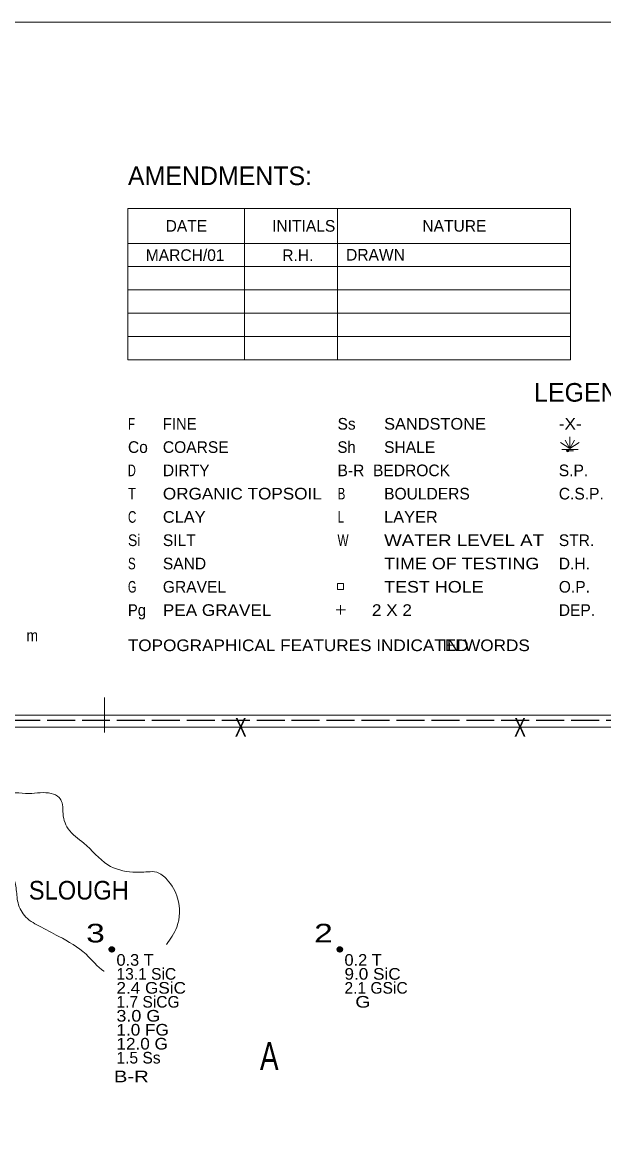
# Model space of a CAD drawing. Extents: x -577 to 499, y -450 to 700.
# Drawn here: x -35.4 to 214.3, y 225.1 to 700 of the extents above; entities that cross this region are included whole.
import ezdxf
from ezdxf.enums import TextEntityAlignment as Align

# ---------------------------------------------------------------- set-up
doc = ezdxf.new("R2010")
doc.units = 0
doc.header["$LTSCALE"] = 2
doc.header["$PDMODE"] = 32
doc.header["$PDSIZE"] = 1
doc.linetypes.add('LONG_DASHED', pattern=[7.5, 6, -1.5])
for name, color, linetype, lineweight in [('1', 7, 'Continuous', 13), ('2', 7, 'Continuous', 35), ('3', 7, 'Continuous', 13), ('4', 7, 'Continuous', 25)]:
    doc.layers.add(name, color=color, linetype=linetype, lineweight=lineweight)

msp = doc.modelspace()

# ---------------------------------------------------------------- linework, layer by layer
at = {"layer": '1'}
for p, q in [((199.983, 619.973), (9.983, 619.973)), ((9.983, 619.973), (9.983, 554.973)), ((59.983, 619.973), (59.983, 554.973)), ((99.983, 619.973), (99.983, 554.973)), ((199.983, 554.973), (199.983, 619.973)), ((9.983, 604.973), (199.983, 604.973)), ((9.983, 594.973), (199.983, 594.973)), ((9.983, 584.973), (199.983, 584.973)), ((9.983, 574.973), (199.983, 574.973)), ((9.983, 564.973), (199.983, 564.973)), ((199.76, 516.875), (195.76, 519.375)), ((199.76, 516.875), (197.76, 520.375)), ((199.76, 516.875), (199.76, 521.875)), ((199.76, 516.875), (201.76, 520.375)), ((199.76, 516.875), (203.76, 519.375)), ((196.26, 516.375), (203.26, 516.375)), ((198.26, 515.875), (201.26, 515.875)), ((103.353, 447.618), (99.353, 447.618)), ((101.291, 449.597), (101.291, 445.597)), ((-0.017, 394.973), (-0.017, 409.973))]:
    msp.add_line(p, q, dxfattribs=at)
for points in [[(449.983, -450.027), (449.983, 399.973), (449.983, 699.973), (-450.017, 699.973), (-450.017, 49.973), (-450.017, -450.027)], [(9.983, 554.973), (99.983, 554.973), (199.983, 554.973)], [(402.281, -402.333), (402.281, 402.339), (-402.391, 402.339)]]:
    msp.add_lwpolyline(points, dxfattribs=at)
msp.add_lwpolyline([(99.967, 456.301), (99.967, 458.832), (102.499, 458.832), (102.499, 456.301)], close=True, dxfattribs=at)
msp.add_point((198.76, 515.875), dxfattribs=at)
at = {"layer": '2', "linetype": 'LONG_DASHED', "lineweight": 25}
msp.add_lwpolyline([(302.281, 400), (-302.391, 400), (-302.391, 340.778)], dxfattribs=at)
at = {"layer": '2'}
for centre in [(3.055, 301.751), (100.962, 301.751)]:
    msp.add_circle(centre, 1, dxfattribs=at)
for points in [[(3.045, 302.638), (3.775, 302.234), (3.927, 301.386), (3.241, 300.858), (2.433, 301.088), (2.146, 301.846), (2.393, 302.408), (2.966, 302.576), (3.64, 302.082), (3.623, 301.341), (3.107, 301.082), (2.584, 301.251), (2.36, 301.897), (2.944, 302.363), (3.382, 301.829), (3.342, 301.346), (2.713, 301.481), (2.859, 302.116), (3.152, 301.565)], [(100.951, 302.638), (101.682, 302.234), (101.833, 301.386), (101.148, 300.858), (100.339, 301.088), (100.053, 301.846), (100.3, 302.408), (100.873, 302.576), (101.547, 302.082), (101.53, 301.341), (101.013, 301.082), (100.491, 301.251), (100.266, 301.897), (100.85, 302.363), (101.288, 301.829), (101.249, 301.346), (100.62, 301.481), (100.766, 302.116), (101.058, 301.565)]]:
    msp.add_spline(points, degree=3, dxfattribs=at)
at = {"layer": '2', "linetype": 'LONG_DASHED', "lineweight": 25}
msp.add_spline([(-281.328, 231.83), (-241.679, 217.766), (-223.152, 212.214), (-193.508, 201.481), (-159.789, 189.267), (-142.373, 182.975), (-121.622, 170.021), (-93.831, 153.735), (-76.045, 143.372), (-61.223, 137.08), (-27.503, 125.977), (-5.271, 120.055), (10.663, 117.094), (19.186, 115.613), (29.19, 118.204), (41.048, 124.496), (50.682, 128.937), (63.281, 140.411)], degree=3, dxfattribs=at)
at = {"layer": '3'}
msp.add_line((402.29, 397.182), (-112.541, 397.182), dxfattribs=at)
for points in [[(-45.877, 365.692), (-43.309, 367.937), (-32.557, 368.738), (-22.927, 368.738), (-19.557, 366.975), (-18.273, 364.731), (-17.952, 361.044), (-15.705, 353.51), (-8.965, 347.418), (1.306, 338.121), (12.059, 334.914), (18.479, 335.075), (22.33, 334.914), (26.824, 331.708), (31.318, 323.693), (30.997, 311.35), (26.537, 303.9)], [(-0.255, 292.406), (-0.299, 292.434), (-8.002, 299.648), (-19.718, 307.343), (-28.223, 311.831), (-34.483, 316.319), (-37.371, 322.571), (-38.174, 328.983), (-42.507, 339.724), (-46.519, 356.876), (-45.877, 365.212)]]:
    msp.add_spline(points, degree=3, dxfattribs=at)

# ---------------------------------------------------------------- texts
at = {"layer": '1'}
for s, height, p in [('AMENDMENTS:', 8, (9.983, 629.973)), ('Ss', 5, (99.983, 524.973)), ('Co', 5, (9.983, 514.973)), ('COARSE', 5, (24.983, 514.973)), ('SHALE', 5, (119.983, 514.973)), ('DIRTY', 5, (24.983, 504.973)), ('B-R  BEDROCK', 5, (99.983, 504.973)), ('S.P.', 5, (194.983, 504.973)), ('BOULDERS', 5, (119.983, 494.973)), ('C.S.P.', 5, (194.983, 494.973)), ('SILT', 5, (24.983, 474.973)), ('STR.', 5, (194.983, 474.973)), ('SAND', 5, (24.983, 464.973)), ('D.H.', 5, (194.983, 464.973)), ('GRAVEL', 5, (24.983, 454.973)), ('O.P.', 5, (194.983, 454.973)), ('DEP.', 5, (194.983, 444.973))]:
    msp.add_text(s, height=height, dxfattribs=at).set_placement(p)
for s, height, p in [('DATE', 5, (35.081, 609.973)), ('INITIALS', 5, (85.453, 609.973)), ('NATURE', 5, (150.16, 609.973)), ('MARCH/01', 5, (34.552, 597.405)), ('R.H.', 5, (82.941, 597.343)), ('DRAWN', 5, (116.266, 597.567)), ('LEGEND', 8, (206.378, 536.973))]:
    msp.add_text(s, height=height, dxfattribs=at).set_placement(p, align=Align.CENTER)
for s, width, p in [('F', 0.75, (9.983, 524.973)), ('FINE', 0.95, (24.983, 524.973)), ('SANDSTONE', 1.05, (119.983, 524.973)), ('-X-', 1.1, (194.983, 524.973)), ('Sh', 0.95, (99.983, 514.973)), ('D', 0.7, (9.983, 504.973)), ('T', 0.85, (9.983, 494.973)), ('ORGANIC TOPSOIL', 1.1, (24.983, 494.973)), ('B', 0.75, (99.983, 494.973)), ('C', 0.75, (9.983, 484.973)), ('CLAY', 1.05, (24.983, 484.973)), ('L', 0.75, (99.983, 484.973)), ('LAYER', 1.05, (119.983, 484.973)), ('Si', 0.9, (9.983, 474.973)), ('W', 0.75, (99.983, 474.973)), ('WATER LEVEL AT', 1.2, (119.983, 474.973)), ('S', 0.75, (9.983, 464.973)), ('TIME OF TESTING', 1.15, (119.983, 464.973)), ('G', 0.7, (9.983, 454.973)), ('TEST HOLE', 1.15, (119.983, 454.973)), ('Pg', 0.95, (9.983, 444.973)), ('PEA GRAVEL', 1.1, (24.983, 444.973)), ('   2 X 2', 1.1, (108.608, 444.973)), ('m', 0.9, (-33.607, 434.073)), ('TOPOGRAPHICAL FEATURES INDICATED', 1.1, (9.942, 429.855)), ('IN WORDS', 1.1, (144.942, 429.855))]:
    msp.add_text(s, height=5, dxfattribs=dict(at, width=width)).set_placement(p)
at = {"layer": '2', "width": 1.35}
for s, p in [('  3', (0.055, 304.751)), ('  2', (97.962, 304.751))]:
    msp.add_text(s, height=8, dxfattribs=at).set_placement(p, align=Align.RIGHT)
at = {"layer": '2'}
for s, width, p in [('0.3 T      ', 1.05, (5.055, 294.751)), ('0.2 T      ', 1.05, (102.962, 294.751)), ('9.0 SiC    ', 1.1, (102.962, 288.751)), ('2.4 GSiC   ', 1.1, (5.055, 282.751)), ('  G        ', 1.25, (102.962, 276.751)), ('3.0 G      ', 1.15, (5.055, 270.751)), ('1.0 FG     ', 1.1, (5.055, 264.751)), ('12.0 G     ', 1.1, (5.055, 258.751)), ('  B-R      ', 1.3, (-0.871, 244.712))]:
    msp.add_text(s, height=5, dxfattribs=dict(at, width=width)).set_placement(p)
for s, p in [('13.1 SiC   ', (5.055, 288.751)), ('2.1 GSiC   ', (102.962, 282.751)), ('1.7 SiCG   ', (5.055, 276.751)), ('1.5 Ss     ', (5.055, 252.751))]:
    msp.add_text(s, height=5, dxfattribs=at).set_placement(p)
at = {"layer": '2', "width": 0.75}
msp.add_text('A', height=12, dxfattribs=at).set_placement((70.673, 249.925), align=Align.CENTER)
at = {"layer": '3', "width": 0.7}
for p in [(58.405, 393.166), (178.33, 393.182)]:
    msp.add_text('X', height=8, dxfattribs=at).set_placement(p, align=Align.CENTER)
at = {"layer": '4', "width": 0.95}
msp.add_text('SLOUGH', height=8, dxfattribs=at).set_placement((-11.116, 323.167), align=Align.CENTER)

doc.saveas('drawing.dxf')
